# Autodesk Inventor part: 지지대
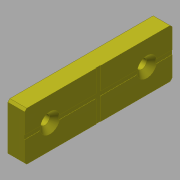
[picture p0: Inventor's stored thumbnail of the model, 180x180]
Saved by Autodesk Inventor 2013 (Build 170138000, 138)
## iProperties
Created: 2017-04
Part Number: 지지대
Material: 강철
Document SubType Name: Modeling
Designer: mduedu
Density: 7.85 g/cm^3
Mass: 97.8486 g
Surface Area: 48.4895 cm^2
Volume: 12.4648 cm^3
Author: mduedu
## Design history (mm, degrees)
sketch "스케치1"
  geometry: L1 (23, -35)-(23, 35); L2 (0, -35)-(0, 35); L3 (0, 35)-(23, 35); L4 (0, -35)-(23, -35); 2 further points
  constraints: 8 end point, 2 parallel, 1 coincident, 1 midpoint, 1 perpendicular, 1 vertical
  dimensions: "d1" = 23 distance between parallel lines of L2 L1; "d15" = 70 distance of L1.start L1.end
extrude "돌출1" new body sketch "스케치1" distance "d2" = 8; taper "d3" = 0 deg
chamfer "모따기2" distance "d16" = 1; stored, may be unused: second distance "d17" = 2, angle "d18" = 45 deg
sketch "스케치2"
  geometry: L1 (1, -35)-(22, -35) reference; L2 (23, -34)-(23, 34) reference; L3 (22, 35)-(1, 35) reference; L4 (0, 34)-(0, -34) reference; L5 (11.5, 35)-(11.5, -35); L6 (23, 0)-(0, 0); L7 (1, -35)-(0, -34) reference; L8 (23, -34)-(22, -35) reference; L9 (22, 35)-(23, 34) reference; L10 (0, 34)-(1, 35) reference; 2 further points
  constraints: 4 end point, 4 midpoint, 1 point on line, 1 symmetric about line
  dimensions: "d7" = 12 distance from line of point (11.5, 23) L3
  node "투영된 루프1"
sketch "스케치3"
  geometry: 4 further points
  constraints: 2 coincident
hole "구멍1" sketch "스케치3" at (11.5, 23), (11.5, -23) diameter "d8" = 4.5; stored, may be unused: countersink angle "d12" = 90 deg, drill point angle "d14" = 0 deg; dims "d9" = 6, "d10" = 9.4, "d11" = 2, "d13" = 8
sketch "스케치4"
  geometry: L1 (-35, 22)-(-35, 1) reference; L2 (35, 1)-(35, 22) reference; L3 (34, 23)-(-34, 23) reference; L4 (-34, 0)-(34, 0) reference; L5 (-35, 11.5)-(35, 11.5); L6 (0, 23)-(0, 0); L7 (-35, 12.5)-(35, 12.5); L8 (-35, 10.5)-(35, 10.5); L9 (-1, 23)-(-1, 0); L10 (1, 23)-(1, 0)
  constraints: 12 end point, 8 point on line, 4 parallel, 3 midpoint, 3 perpendicular
  dimensions: "d19" = 1 distance between parallel lines of L7 L5; "d21" = 1 distance between parallel lines of L8 L5; "d22" = 1 distance between parallel lines of L9 L6; "d23" = 1 distance between parallel lines of L10 L6
extrude "돌출2" cut sketch "스케치4" distance "d24" = 0.2; taper "d25" = 0 deg
extrude "돌출3" cut sketch "스케치4" distance "d26" = 0.2; taper "d27" = 0 deg
fillet "모깎기1" dims "d28" = 0.2
node "솔리드2"
node "솔리드1"
